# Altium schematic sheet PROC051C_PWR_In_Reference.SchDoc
size 431 x 279 mm; Date: Not shown in title block; ApprovedBy: Not shown in title block; CheckedBy: Not shown in title block; Author: Not shown in title block; CompanyName: Not shown in title block; Engineer: Not shown in title block; Organization: Not shown in title block; Address1: Not shown in title block; Address2: Not shown in title block; Address3: Not shown in title block; Address4: Not shown in title block; DocumentNumber: 4; Revision: Use project parameter SCH_Rev; SheetNumber: 4; SheetTotal: 16; PageSetup: Record=PageOptions¦CenterHorizontal=True¦CenterVertical=True¦PrintScale=1.00¦XCorrection=1.00¦YCorrection=1.00¦PrintKind=0¦BorderSize=5000000¦LeftOffset=0¦BottomOffset=0¦Orientation=2¦PaperLength=1000¦PaperWidth=1000¦Scale=100¦PaperSource=15¦PrintQuality=600¦MediaType=1¦DitherType=10¦PaperKind=Letter¦PrintScaleMode=1
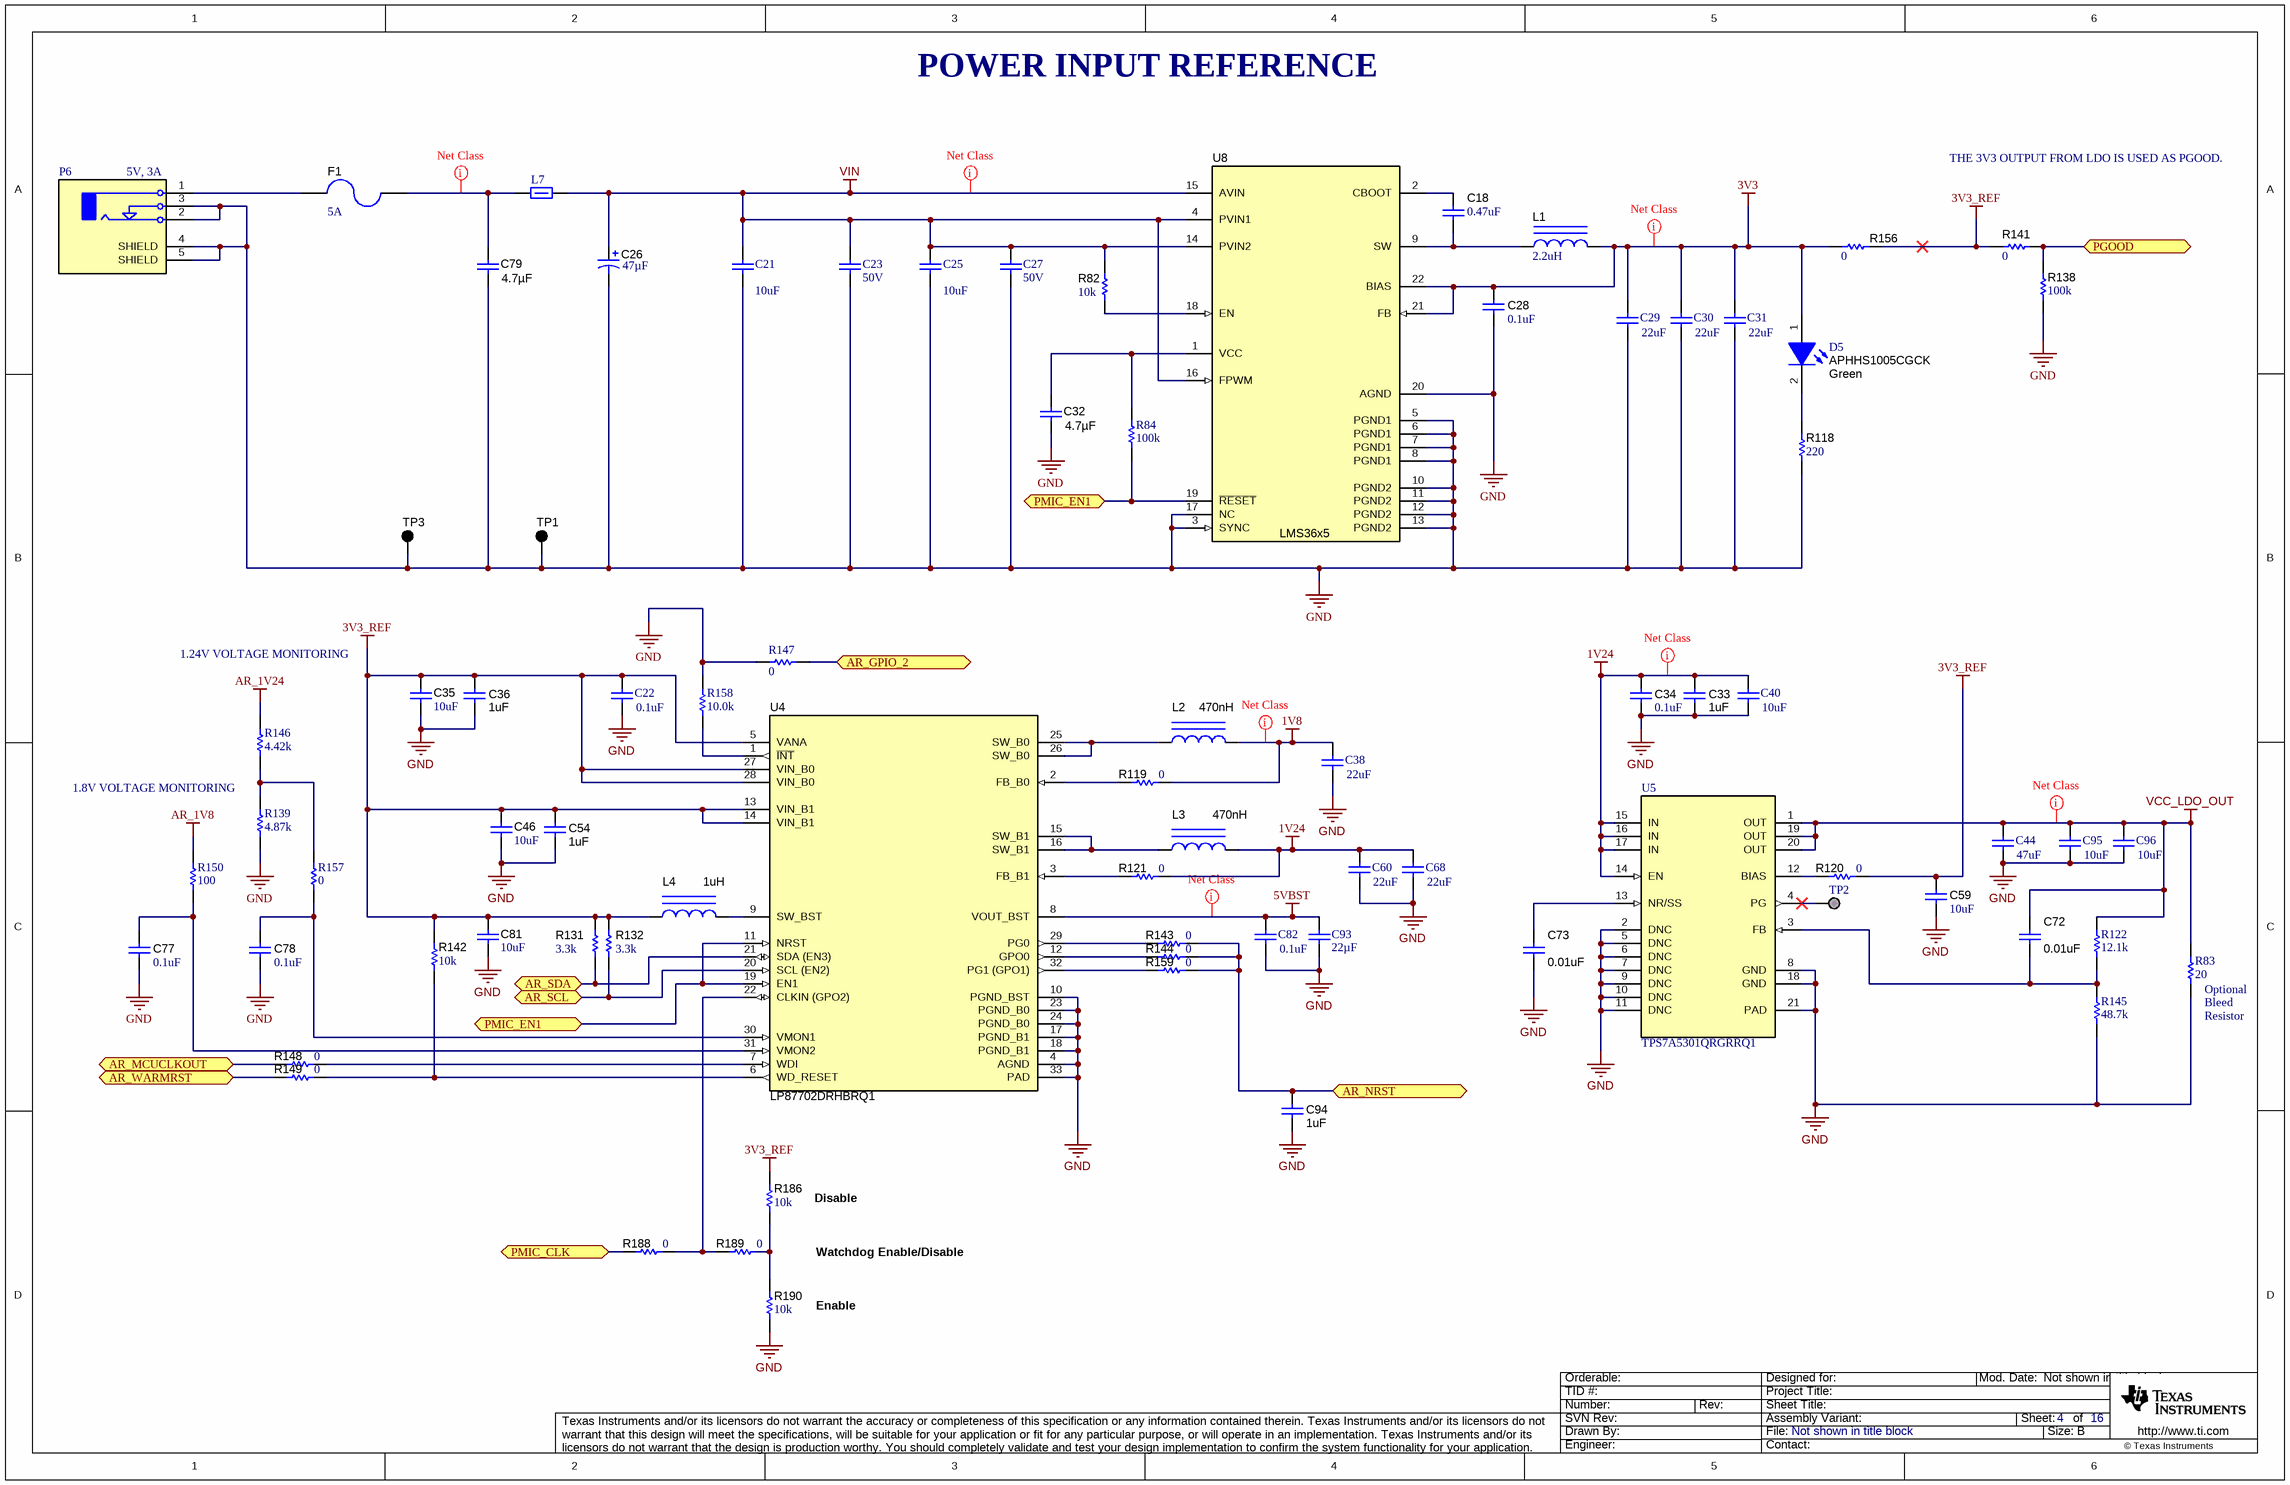
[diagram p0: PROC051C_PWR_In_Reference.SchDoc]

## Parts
C18  ValueDisplayed: 0.47uF  [0402S]  (hidden comment: Capacitor)
C21  ValueDisplayed: 10uF  [1210_280]  (hidden comment: CGA6P1X7R1E106M250AC)
C22  ValueDisplayed: 0.1uF  [0402]  (hidden comment: GCM155R71C104KA55D)
C23  VDC_V: 50V  [0603]  (hidden comment: 06035C473JAT2A)
C25  ValueDisplayed: 10uF  [1210_280]  (hidden comment: CGA6P1X7R1E106M250AC)
C26  ValueDisplayed: 47µF  [3528-21]  (hidden comment: T491B476K010AT)
C27  VDC_V: 50V  [0603]  (hidden comment: 06035C473JAT2A)
C28  ValueDisplayed: 0.1uF  [0402S]  (hidden comment: Capacitor)
C29  ValueDisplayed: 22uF  [1210_280]  (hidden comment: GCM32ER71C226KE19L)
C30  ValueDisplayed: 22uF  [1210_280]  (hidden comment: GCM32ER71C226KE19L)
C31  ValueDisplayed: 22uF  [1210_280]  (hidden comment: GCM32ER71C226KE19L)
C32  ValueDisplayed: 4.7µF  [0805L]  (hidden comment: CGA4J1X7R1E475K125AC)
C33  ValueDisplayed: 1uF  [0603]  (hidden comment: GCM188R71C105KA64D)
C34  ValueDisplayed: 0.1uF  [0402]  (hidden comment: Capacitor)
C35  ValueDisplayed: 10uF  [0805_HV1]  (hidden comment: Capacitor)
C36  ValueDisplayed: 1uF  [0603]  (hidden comment: GCM188R71C105KA64D)
C38  ValueDisplayed: 22uF  [1206_180]  (hidden comment: GCM31CR70J226KE23L)
C40  ValueDisplayed: 10uF  [0805_HV]  (hidden comment: GCM21BR71A106KE22L)
C44  ValueDisplayed: 47uF  [1210_270]  (hidden comment: GCM32ER70J476KE19L)
C46  ValueDisplayed: 10uF  [0805_HV1]  (hidden comment: Capacitor)
C54  ValueDisplayed: 1uF  [0603]  (hidden comment: GCM188R71C105KA64D)
C59  ValueDisplayed: 10uF  [0805_HV]  (hidden comment: Capacitor)
C60  ValueDisplayed: 22uF  [1206_180]  (hidden comment: GCM31CR70J226KE23L)
C68  ValueDisplayed: 22uF  [1206_180]  (hidden comment: GCM31CR70J226KE23L)
C72  ValueDisplayed: 0.01uF  [0402S]  (hidden comment: GCM155R71E103KA37D)
C73  ValueDisplayed: 0.01uF  [0402S]  (hidden comment: GCM155R71E103KA37D)
C77  ValueDisplayed: 0.1uF  [0402]  (hidden comment: Capacitor)
C78  ValueDisplayed: 0.1uF  [0402]  (hidden comment: Capacitor)
C79  ValueDisplayed: 4.7µF  [0805L]  (hidden comment: CGA4J1X7R1E475K125AC)
C81  ValueDisplayed: 10uF  [0805_HV1]  (hidden comment: Capacitor)
C82  ValueDisplayed: 0.1uF  [0402]  (hidden comment: 0402YC104KAT2A)
C93  ValueDisplayed: 22µF  [0805_HV]  (hidden comment: GRT21BR61E226ME13L)
C94  ValueDisplayed: 1uF  [0603]  (hidden comment: GCM188R71C105KA64D)
C95  ValueDisplayed: 10uF  [0805_HV]  (hidden comment: GCM21BR71A106KE22L)
C96  ValueDisplayed: 10uF  [0805_HV]  (hidden comment: GCM21BR71A106KE22L)
D5  APHHS1005CGCK  value Green  [APHHS1005_Green]
F1  0440005.WR  [1206]  (value not drawn)
L1  ValueDisplayed: 2.2uH  [XAL5030]  (hidden comment: XAL5030-222MEB)
L2  ValueDisplayed: 470nH  [DFE252012P]  (hidden comment: DFE252012PD-R47M)
L3  ValueDisplayed: 470nH  [DFE252012P]  (hidden comment: DFE252012PD-R47M)
L4  ValueDisplayed: 1uH  [DFE252012P]  (hidden comment: DFE252012PD-1R0M)
L7  HI2220P601R-10  [2220_345]  (value not drawn)
P6  PJ-051AH  [CUI_PJ-051AH]  (value not drawn)
R82  value 10k  [0402L]  (hidden comment: Resistor)
R83  ValueDisplayed: 20  [0603]  (hidden comment: CRCW060320R0JNEA)
R84  ValueDisplayed: 100k  [0402]  (hidden comment: CRCW0402100KJNED)
R118  ValueDisplayed: 220  [0402]  (hidden comment: CRCW0402220RJNED)
R119  value 0  [0402L]  (hidden comment: Resistor)
R120  value 0  [0402L]  (hidden comment: Resistor)
R121  value 0  [0402L]  (hidden comment: Resistor)
R122  ValueDisplayed: 12.1k  [0402]  (hidden comment: ERA-2AEB1212X)
R131  ValueDisplayed: 3.3k  [0402S]  (hidden comment: Resistor)
R132  ValueDisplayed: 3.3k  [0402S]  (hidden comment: Resistor)
R138  ValueDisplayed: 100k  [0402L]  (hidden comment: CRCW0402100KFKED)
R139  ValueDisplayed: 4.87k  [0402]  (hidden comment: ERA-2AEB4871X)
R141  ValueDisplayed: 0  [0402L]  (hidden comment: ERJ-2GE0R00X)
R142  ValueDisplayed: 10k  [0402]  (hidden comment: CRCW040210K0JNED)
R143  value 0  [0402L]  (hidden comment: Resistor)
R144  value 0  [0402L]  (hidden comment: Resistor)
R145  ValueDisplayed: 48.7k  [0402]  (hidden comment: ERA-2AEB4872X)
R146  ValueDisplayed: 4.42k  [0402]  (hidden comment: ERA-2ARB4421X)
R147  ValueDisplayed: 0  [0402]  (hidden comment: CRCW04020000Z0ED)
R148  value 0  [0402L]  (hidden comment: Resistor)
R149  value 0  [0402L]  (hidden comment: Resistor)
R150  ValueDisplayed: 100  [0402]  (hidden comment: CRCW0402100RFKED)
R156  ValueDisplayed: 0  [2010]  (hidden comment: CRCW20100000Z0EF)
R157  ValueDisplayed: 0  [0402]  (hidden comment: CRCW04020000Z0ED)
R158  ValueDisplayed: 10.0k  [0402]  (hidden comment: CRCW040210K0FKED)
R159  value 0  [0402L]  (hidden comment: Resistor)
R186  ValueDisplayed: 10k  [0402]  (hidden comment: CRCW040210K0JNED)
R188  value 0  [0402L]  (hidden comment: Resistor)
R189  value 0  [0402L]  (hidden comment: Resistor)
R190  ValueDisplayed: 10k  [0402]  (hidden comment: CRCW040210K0JNED)
TP1  5001  [Keystone5001]  (value not drawn)
TP2  TP_H0.45P0.75  [TP_H045P075]  (value not drawn)  (no BOM)
TP3  5001  [Keystone5001]  (value not drawn)
U4  LP87702DRHBRQ1  [RHB0032N]
U5  TPS7A5301QRGRRQ1  [RGR0020A]
U8  LMS36x5  [RNL0022A_NV]

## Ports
AR_GPIO_2, AR_MCUCLKOUT, AR_NRST, AR_SCL, AR_SDA, AR_WARMRST, PGOOD, PMIC_CLK, PMIC_EN1

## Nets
1V8: C38.1 L2.2 R119.1
1V24: C33.2 C34.1 C40.1 C60.1 C68.1 L3.2 R121.1 U5.14(EN) U5.15(IN) U5.16(IN) U5.17(IN)
3V3: C28.1 C29.1 C30.1 C31.1 D5.1(A) L1.2 R156.1 U8.21(FB) U8.22(BIAS)
3V3_REF: C22.1 C35.1 C36.2 C46.1 C54.2 C59.1 C81.1 L4.1 R120.1 R131.2 R132.2 R141.1 R142.2 R156.2 R186.2 U4.5(VANA) U4.13(VIN_B1) U4.14(VIN_B1) U4.27(VIN_B0) U4.28(VIN_B0)
5VBST: C82.1 C93.1 U4.8(VOUT_BST)
AR_1V8: R150.2
AR_1V24: R146.2
GND: C21.2 C22.2 C23.2 C25.2 C26.2(-) C27.2 C28.2 C29.2 C30.2 C31.2 C32.2 C33.1 C34.2 C35.2 C36.1 C38.2 C40.2 C44.2 C46.2 C54.1 C59.2 C60.2 C68.2 C73.2 C77.2 C78.2 C79.2 C81.2 C82.2 C93.2 C94.1 C95.2 C96.2 P6.2(TIP) P6.3(TIP_SWITCH) P6.4(SHIELD) P6.5(SHIELD) R83.1 R118.1 R138.1 R139.1 R145.1 R147.2 R158.2 R190.1 TP1.1 TP3.1 U4.4(AGND) U4.10(PGND_BST) U4.17(PGND_B1) U4.18(PGND_B1) U4.23(PGND_B0) U4.24(PGND_B0) U4.33(PAD) U5.2(DNC) U5.5(DNC) U5.6(DNC) U5.7(DNC) U5.8(GND) U5.9(DNC) U5.10(DNC) U5.11(DNC) U5.18(GND) U5.21(PAD) U8.3(SYNC) U8.5(PGND1) U8.6(PGND1) U8.7(PGND1) U8.8(PGND1) U8.10(PGND2) U8.11(PGND2) U8.12(PGND2) U8.13(PGND2) U8.17(NC) U8.20(AGND)
VCC_LDO_OUT: C44.1 C72.1 C95.1 C96.1 R83.2 R122.2 U5.1(OUT) U5.19(OUT) U5.20(OUT)
VIN: C21.1 C23.1 C25.1 C26.1(+) C27.1 L7.2 R82.1 U8.4(PVIN1) U8.14(PVIN2) U8.15(AVIN) U8.16(FPWM)
AR_GPIO_2: R147.1 ; port AR_GPIO_2
AR_MCUCLKOUT: R148.2 ; port AR_MCUCLKOUT
AR_NRST: C94.2 R143.1 R144.1 R159.1 ; port AR_NRST
AR_SCL: R132.1 U4.20(SCL_(EN2)) ; port AR_SCL
AR_SDA: R131.1 U4.21(SDA_(EN3)) ; port AR_SDA
AR_WARMRST: R149.2 ; port AR_WARMRST
PGOOD: R138.2 R141.2 ; port PGOOD
PMIC_CLK: R188.2 ; port PMIC_CLK
PMIC_EN1: R84.1 U4.11(NRST) U4.19(EN1) U8.19(~{RESET}) ; port PMIC_EN1
NetC18_1: C18.1 U8.2(CBOOT)
NetC18_2: C18.2 L1.1 U8.9(SW)
NetC32_1: C32.1 R84.2 U8.1(VCC)
NetC72_2: C72.2 R122.1 R145.2 U5.3(FB)
NetC73_1: C73.1 U5.13(NR/SS)
NetC77_1: C77.1 R150.1 U4.31(VMON2)
NetC78_1: C78.1 R157.1 U4.30(VMON1)
NetC79_1: C79.1 F1.1 L7.1
NetD5_2: D5.2(K) R118.2
NetF1_2: F1.2 P6.1(SLEEVE)
NetL2_1: L2.1 U4.25(SW_B0) U4.26(SW_B0)
NetL3_1: L3.1 U4.15(SW_B1) U4.16(SW_B1)
NetL4_2: L4.2 U4.9(SW_BST)
NetR82_2: R82.2 U8.18(EN)
NetR119_2: R119.2 U4.2(FB_B0)
NetR120_2: R120.2 U5.12(BIAS)
NetR121_2: R121.2 U4.3(FB_B1)
NetR139_2: R139.2 R146.1 R157.2
NetR142_1: R142.1 R149.1 U4.6(WD_RESET)
NetR143_2: R143.2 U4.29(PG0)
NetR144_2: R144.2 U4.12(GPO0)
NetR148_1: R148.1 U4.7(WDI)
NetR158_1: R158.1 U4.1(~{INT})
NetR159_2: R159.2 U4.32(PG1_(GPO1))
NetR186_1: R186.1 R189.1 R190.2
NetR188_1: R188.1 R189.2 U4.22(CLKIN_(GPO2))
NetTP2_1: TP2.1 U5.4(PG)

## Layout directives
net class Undefined: VCC_LDO_OUT
net class PWR: 1V8, 1V24, 3V3, 5VBST, NetC79_1, VIN

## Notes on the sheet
- POWER INPUT REFERENCE
- THE 3V3 OUTPUT FROM LDO IS USED AS PGOOD.
- (near P6) 5V, 3A
- (near F1) 5A
- 1.24V VOLTAGE MONITORING
- 1.8V VOLTAGE MONITORING
- (near R83) Optional
- (near R83) Bleed
- (near R83) Resistor
- (near R186) Disable
- (near R190) Enable
- Watchdog Enable/Disable

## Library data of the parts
C18 = CMP-0006717-2: CAP, CERM, 0.47 uF, 6.3 V, +/- 10%, X7R, 0402; PartNumber: JMK105B7474KVHF; Manufacturer: Taiyo Yuden; Polarized: N; Value: 0.47uF; U/M: EA; Cap_F: 470nF; Value1: Unknown; VDC_V: 6.3V; TaMin_C: -55°C; TaMax_C: 125°C; Cap_Case: 0402; SizeArea_mm2: 0.5; SizeAreaWB_mm2: 3; SizeX_mm: 1; SizeZ_mm: 0.6; AEC Category: Q200
C21 C25 = CMP-0009155-2: CAP, CERM, 10 uF, 25 V, +/- 20%, X7R, AEC-Q200 Grade 1, 1210; Manufacturer: TDK; TaMin_C: -55°C; Polarized: N; SizeAreaWB_mm2: 14.7; Value1: Unknown; U/M: EA; Value: 10uF; TaMax_C: 125°C; SizeZ_mm: 2.8; SizeX_mm: 3.2; SizeY_mm: 2.5; Cap_Case: 1210; Value2: 25V; SizeArea_mm2: 8; AEC Qualified: Y; Cap_F: 10µF; AEC Grade: 1; AEC Category: Q200
C22 = CMP-0006351-2: CAP, CERM, 0.1 uF, 16 V, +/- 10%, X7R, 0402; Manufacturer: MuRata; TaMin_C: -55°C; Polarized: N; SizeAreaWB_mm2: 3; Value1: Unknown; U/M: EA; Value: 0.1uF; TaMax_C: 125°C; SizeZ_mm: 0.6; SizeX_mm: 1; SizeY_mm: 0.5; Value2: 16V; Cap_F: 100nF; AEC Category: Q200
C23 C27 = CMP-0085252-1: CAP, CERM, 0.047 µF, 50 V,+/- 5%, X7R, 0603; Manufacturer: AVX; Cap_F: 47nF; TaMax_C: 125°C; Value: 0.047uF; SizeX_mm: 1.6; SizeArea_mm2: 1.28; AEC Category: Q200; SizeY_mm: 0.8; Polarized: N; SizeAreaWB_mm2: 4.68; U/M: EA; TaMin_C: -55°C; SizeZ_mm: 1
C26 = CMP-0078216-1: CAP, TA, 47 µF, 10 V, +/- 10%, SMD; Manufacturer: Kemet; TaMin_C: -55°C; Polarized: Y; SizeAreaWB_mm2: 17.1; Value: 47uF; TaMax_C: 125°C; SizeZ_mm: 2.1; SizeX_mm: 3.5; SizeY_mm: 2.8; Value2: 10V; SizeArea_mm2: 9.8; CompType: Capacitor; AEC Qualified: N; AEC Category: Q200
C28 = CMP-0006201-2: CAP, CERM, 0.1 uF, 16 V, +/- 10%, X7R, 0402; PartNumber: 0402YC104KAT2A; Manufacturer: AVX; Polarized: N; Value: 0.1uF; U/M: EA; Cap_F: 100nF; Value1: Unknown; VDC_V: 16V; TaMin_C: -55°C; TaMax_C: 125°C; Cap_Case: 0402; SizeArea_mm2: 0.5; SizeAreaWB_mm2: 3; SizeX_mm: 1; SizeZ_mm: 0.6; AEC Category: Q200
C29-C31 = CMP-0009174-2: CAP, CERM, 22 uF, 16 V, +/- 10%, X7R, 1210; Manufacturer: MuRata; TaMin_C: -55°C; Polarized: N; SizeAreaWB_mm2: 14.7; Value1: Unknown; U/M: EA; Value: 22uF; TaMax_C: 125°C; SizeZ_mm: 2.8; SizeX_mm: 3.2; SizeY_mm: 2.5; Cap_Case: 1210; Value2: 16V; SizeArea_mm2: 8; Cap_F: 22µF; AEC Category: Q200
C32 C79 = CMP-0076706-1: CAP, CERM, 4.7 µF, 25 V,+/- 10%, X7R, AEC-Q200 Grade 1, 0805; Manufacturer: TDK; SizeAreaWB_mm2: 6.75; SizeArea_mm2: 2.5; AEC Qualified: Y; AEC Category: Q200; Value: 4.7uF; TaMax_C: 125°C; SizeZ_mm: 1.45; AEC Grade: 1; Polarized: N; TaMin_C: -55°C; VDC_V: 25V; SizeY_mm: 1.25; U/M: EA; CompType: Capacitor; SizeX_mm: 2.0; Cap_Case: 2x1.25x1.25mm
C33 C36 C54 C94 = CMP-0007136-5: CAP, CERM, 1 uF, 16 V, +/- 10%, X7R, AEC-Q200 Grade 1, 0603; Manufacturer: MuRata; TaMin_C: -55°C; Polarized: N; SizeAreaWB_mm2: 4.68; Value1: Unknown; U/M: EA; Value: 1uF; TaMax_C: 125°C; SizeZ_mm: 1; SizeX_mm: 1.6; SizeY_mm: 0.8; Value2: 16V; SizeArea_mm2: 1.28; AEC Qualified: Y; Cap_F: 1µF; AEC Category: Q200
C34 C77 C78 = CMP-0006201-2: CAP, CERM, 0.1 uF, 16 V, +/- 10%, X7R, 0402; PartNumber: 0402YC104KAT2A; Manufacturer: AVX; Polarized: N; Value: 0.1uF; U/M: EA; Cap_F: 100nF; Value1: Unknown; VDC_V: 16V; TaMin_C: -55°C; TaMax_C: 125°C; SizeArea_mm2: 0.5; SizeAreaWB_mm2: 3; SizeX_mm: 1; SizeZ_mm: 0.6; AEC Category: Q200
C35 C46 C81 = CMP-0007995-2: CAP, CERM, 10 uF, 16 V, +/- 10%, X7R, 0805; PartNumber: CL21B106KOQNNNE; Manufacturer: Samsung Electro-Mechanics; Polarized: N; Value: 10uF; U/M: EA; Cap_F: 10µF; Value1: Unknown; VDC_V: 16V; TaMin_C: -55°C; TaMax_C: 125°C; Cap_Case: 0805; SizeArea_mm2: 2.5; SizeAreaWB_mm2: 6.75; SizeX_mm: 2; SizeY_mm: 1.25; SizeZ_mm: 1.45; AEC Category: Q200
C38 C60 = CMP-0008809-2: CAP, CERM, 22 uF, 6.3 V, +/- 10%, X7R, AEC-Q200 Grade 1, 1206; Manufacturer: MuRata; TaMin_C: -55°C; Polarized: N; SizeAreaWB_mm2: 10.92; Value1: Unknown; U/M: EA; Value: 22uF; TaMax_C: 125°C; SizeZ_mm: 1.8; SizeX_mm: 3.2; SizeY_mm: 1.6; Cap_Case: 1206; Value2: 6.3V; SizeArea_mm2: 5.12; AEC Qualified: Y; Cap_F: 22µF; AEC Grade: 1; AEC Category: Q200
C40 C95 C96 = CMP-0008017-2: CAP, CERM, 10 uF, 10 V, +/- 10%, X7R, 0805; Manufacturer: MuRata; TaMin_C: -55°C; Polarized: N; SizeAreaWB_mm2: 6.75; Value1: Unknown; U/M: EA; Value: 10uF; TaMax_C: 125°C; SizeZ_mm: 1.45; SizeX_mm: 2; SizeY_mm: 1.25; Cap_Case: 0805; Value2: 10V; SizeArea_mm2: 2.5; Cap_F: 10µF; AEC Category: Q200
C44 = CMP-0009172-2: CAP, CERM, 47 uF, 6.3 V, +/- 10%, X7R, AEC-Q200 Grade 1, 1210; Manufacturer: MuRata; TaMin_C: -55°C; Polarized: N; SizeAreaWB_mm2: 14.7; Value1: Unknown; U/M: EA; Value: 47uF; TaMax_C: 125°C; SizeZ_mm: 2.7; SizeX_mm: 3.2; SizeY_mm: 2.5; Cap_Case: 1210; Value2: 6.3V; SizeArea_mm2: 8; AEC Qualified: Y; Cap_F: 47µF; AEC Grade: 1; AEC Category: Q200
C59 = CMP-0008017-2: CAP, CERM, 10 uF, 10 V, +/- 10%, X7R, 0805; PartNumber: GCM21BR71A106KE22L; Manufacturer: MuRata; Polarized: N; Value: 10uF; U/M: EA; Cap_F: 10µF; Value1: Unknown; VDC_V: 10V; TaMin_C: -55°C; TaMax_C: 125°C; Cap_Case: 0805; SizeArea_mm2: 2.5; SizeAreaWB_mm2: 6.75; SizeX_mm: 2; SizeY_mm: 1.25; SizeZ_mm: 1.45; AEC Category: Q200
C68 = CMP-0008809-2: CAP, CERM, 22 uF, 6.3 V, +/- 10%, X7R, AEC-Q200 Grade 1, 1206; Manufacturer: MuRata; TaMin_C: -55°C; Polarized: N; SizeAreaWB_mm2: 10.92; Value1: Unknown; U/M: EA; Value: 22uF; TaMax_C: 125°C; SizeZ_mm: 1.8; SizeX_mm: 3.2; SizeY_mm: 1.6; Cap_Case: 1206; Value2: 6.3V; SizeArea_mm2: 5.12; CompType: Capacitor; AEC Qualified: Y; Cap_F: 22µF; AEC Grade: 1; AEC Category: Q200
C72 C73 = CMP-0006352-2: CAP, CERM, 0.01 uF, 25 V, +/- 10%, X7R, 0402; Manufacturer: MuRata; TaMin_C: -55°C; Polarized: N; SizeAreaWB_mm2: 3; Value1: Unknown; U/M: EA; Value: 0.01uF; TaMax_C: 125°C; SizeZ_mm: 0.6; SizeX_mm: 1; SizeY_mm: 0.5; Cap_Case: 0402; Value2: 25V; CompType: Capacitor; Cap_F: 10nF; AEC Category: Q200
C82 = CMP-0006201-2: CAP, CERM, 0.1 uF, 16 V, +/- 10%, X7R, 0402; Manufacturer: AVX; TaMin_C: -55°C; Polarized: N; SizeAreaWB_mm2: 3; Value1: Unknown; U/M: EA; Value: 0.1uF; TaMax_C: 125°C; SizeZ_mm: 0.6; SizeX_mm: 1; SizeY_mm: 0.5; Value2: 16V; Cap_F: 100nF; AEC Category: Q200
C93 = CMP-0084680-1: CAP, CERM, 22 µF, 25 V,+/- 20%, X5R, AEC-Q200 Grade 3, 0805; Manufacturer: MuRata; SizeX_mm: 2; SizeAreaWB_mm2: 6.75; Cap_Case: 0805; AEC Grade: 3; SizeY_mm: 1.25; SizeArea_mm2: 2.5; SizeZ_mm: 1.45; U/M: EA; Polarized: N; VDC_V: 25V; AEC Category: Q200; Value: 22uF; TaMin_C: -55°C; AEC Qualified: Y; TaMax_C: 85°C
D5 = CMP-0067682-2: LED, Green, SMD; Manufacturer: Kingbright; Io_A: 20mA; Power_TotalModule: 75mW; SizeAreaWB_mm2: 3.0; Vr_V: 5V; Tjmax_C: 85°C; Value1: 0.075W; Angle: 120.0; SizeZ_mm: 0.6; SizeX_mm: 1.0; SizeY_mm: 0.5; Ir_A: 10µA; Vf_V: 2.1V
F1 = CMP-0003458-2: Fuse, 5 A, 32VAC/VDC, SMD; Manufacturer: Littelfuse; Irating_A: 5A; SizeAreaWB_mm2: 10.92; Interrupt_AC: 50A; VAC_V: 32V; SizeZ_mm: 1.35; SizeX_mm: 3.2; SizeY_mm: 1.6; SizeArea_mm2: 5.12; Rtyp_Ohm: 0.012; MeltingTyp: 4.761
L1 = CMP-0061001-2: Inductor, Shielded, Composite, 2.2 µH, 9.2 A, 0.01 ohm, AEC-Q200 Grade 1, SMD; Manufacturer: Coilcraft; Isat: 12.9A @ 30% inductance drop; Irms: 9.2A @ 40C rise; Green_Lifecycle: Not Set; SizeAreaWB_mm2: 54.4544; DCR_ohm: 0.01; Green_REACh: Incomplete; Value: 2.2uH; Imax_A: 9.2A; SizeZ_mm: 3.1; SizeX_mm: 5.28; SizeY_mm: 5.48; SizeArea_mm2: 28.9344; Ind_H: 2.2µH; AEC Qualified: 1; AEC Category: Q200; AEC Grade: Y
L2 L3 = CMP-0058944-1: Inductor, Shielded, 470 nH, 4.7 A, 0.021 ohm, SMD; Manufacturer: MuRata Toko; Isat: 6.1A @ 30% inductance drop; Irms: 4.7A @ 40C rise; SizeAreaWB_mm2: 10.5; DCR_ohm: 0.021; Value: 470nH; Imax_A: 4.7A; SizeZ_mm: 1.2; SizeX_mm: 2.5; SizeY_mm: 2; SizeArea_mm2: 5; AEC Category: Q200
L4 = CMP-0058938-1: Inductor, Shielded, 1 uH, 3.8 A, 0.035 ohm, AEC-Q200 Grade 1, SMD; Manufacturer: MuRata Toko; Isat: 4.5A @ 30% inductance drop; Irms: 3.8A @ 40C rise; SizeAreaWB_mm2: 10.5; DCR_ohm: 0.035; Value: 1uH; Imax_A: 3.8A; SizeZ_mm: 1.2; SizeX_mm: 2.5; SizeY_mm: 2; SizeArea_mm2: 5; Ind_H: 1µH; AEC Qualified: Y; AEC Grade: 1; AEC Category: Q200
L7 = CMP-0003388-1: Ferrite Bead, 600 ohm @ 100 MHz, 4 A, 2220; Manufacturer: Laird-Signal Integrity Products; Ztyp@1GHz_Ohm: 106; ZTyp@100MHz_Ohm: 600; SizeAreaWB_mm2: 53.96; DCR_ohm: 0.025; Value1: 0.025 ohm; Value: 600 ohm; Imax_A: 4A; SizeZ_mm: 3.45; SizeX_mm: 5.6; SizeY_mm: 5.1; SizeArea_mm2: 28.56
P6 = CMP-0081851-1: DC Power Jack, R/A, TH; Manufacturer: CUI Inc.; Gender: Male; Cert_UL: Y; Current_A: 5A; Voltage_V: 24V
R82 = CMP-0026825-5: RES, 10 k, 5%, 0.063 W, AEC-Q200 Grade 0, 0402; PartNumber: CRCW040210K0JNED; Manufacturer: Vishay-Dale; Value_Code: 10k0; Power_W: 63mW; Value2: 0.063W; VDC_V: 50V; TempCo: 200 ppm/C; EIA_Code: E24; AEC Category: Q200; AEC Grade: 0; AEC Qualified: Y; SizeArea_mm2: 0.5; SizeX_mm: 1; SizeZ_mm: 0.6
R83 = CMP-0025754-4: RES, 20, 5%, 0.1 W, AEC-Q200 Grade 0, 0603; Manufacturer: Vishay-Dale; Power_W: 100mW; TempCo: 200 ppm/C; Value_Code: 20R0; Value: 20; EIA_Code: E24; SizeX_mm: 1.6; SizeY_mm: 0.8; SizeZ_mm: 1; Value2: 0.1W; SizeArea_mm2: 1.28; AEC Qualified: Y; VDC_V: 75V; AEC Category: Q200; AEC Grade: 0
R84 = CMP-0026823-3: RES, 100 k, 5%, 0.063 W, AEC-Q200 Grade 0, 0402; Manufacturer: Vishay-Dale; Power_W: 63mW; TempCo: 200 ppm/C; Value: 100k; EIA_Code: E24; SizeX_mm: 1; SizeY_mm: 0.5; SizeZ_mm: 0.6; Value2: 0.063W; AEC Qualified: Y; VDC_V: 50V; AEC Category: Q200; AEC Grade: 0
R118 = CMP-0026878-3: RES, 220, 5%, 0.063 W, AEC-Q200 Grade 0, 0402; Manufacturer: Vishay-Dale; Power_W: 63mW; TempCo: 200 ppm/C; Value_Code: 220R; Value: 220; EIA_Code: E24; SizeX_mm: 1; SizeY_mm: 0.5; SizeZ_mm: 0.6; Value2: 0.063W; AEC Qualified: Y; VDC_V: 50V; AEC Category: Q200; AEC Grade: 0
R119-R121 R143 R144 R148 R149 R159 R188 R189 = CMP-0026822-3: RES, 0, 5%, 0.063 W, AEC-Q200 Grade 0, 0402; PartNumber: CRCW04020000Z0ED; Manufacturer: Vishay-Dale; Value_Code: 0000; Power_W: 63mW; Value2: 0.063W; VDC_V: 50V; TempCo: 200 ppm/C; EIA_Code: E24; AEC Category: Q200; AEC Qualified: Y; SizeArea_mm2: 0.5; SizeX_mm: 1; SizeZ_mm: 0.6
R122 = CMP-0083631-1: RES, 12.1 k, 0.1%, 0.063 W, AEC-Q200 Grade 0, 0402; Manufacturer: Panasonic; Power_W: 63mW; TempCo: 25 ppm/C; SizeAreaWB_mm2: 3; Value_Code: 12k1; Value: 12.1k; EIA_Code: E192; SizeX_mm: 1; SizeY_mm: 0.5; SizeZ_mm: 0.6; Value2: 0.063W; CompType: Resistor; AEC Qualified: Y; VDC_V: 50V; AEC Grade: 0; AEC Category: Q200
R131 R132 = CMP-0026918-5: RES, 3.3 k, 5%, 0.063 W, AEC-Q200 Grade 0, 0402; PartNumber: CRCW04023K30JNED; Manufacturer: Vishay-Dale; Value: 3.3k; Value_Code: 3k30; Power_W: 63mW; Value2: 0.063W; VDC_V: 50V; TempCo: 200 ppm/C; SizeArea_mm2: 0.5; SizeX_mm: 1; SizeZ_mm: 0.6; EIA_Code: E24; AEC Category: Q200; AEC Qualified: Y; AEC Grade: 0
R138 = CMP-0025950-3: RES, 100 k, 1%, 0.063 W, AEC-Q200 Grade 0, 0402; Manufacturer: Vishay-Dale; Power_W: 63mW; TempCo: 100 ppm/C; Value: 100k; EIA_Code: E96; SizeX_mm: 1; SizeY_mm: 0.5; SizeZ_mm: 0.6; Value2: 0.063W; AEC Qualified: Y; VDC_V: 50V; AEC Category: Q200; AEC Grade: 0
R139 = CMP-0026781-1: RES, 4.87 k, 0.1%, 0.062 W, AEC-Q200 Grade 0, 0402; Manufacturer: Panasonic; Power_W: 62mW; TempCo: 25 ppm/C; Value_Code: 4k87; U/M: EA; Value: 4.87k; EIA_Code: E192; SizeX_mm: 1; SizeY_mm: 0.5; SizeZ_mm: 0.6; Value2: 0.062W; AEC Qualified: Y; VDC_V: 25V; AEC Grade: 0; AEC Category: Q200
R141 = CMP-0026992-3: RES, 0, 5%, 0.1 W, AEC-Q200 Grade 0, 0402; Manufacturer: Panasonic; Power_W: 100mW; TempCo: 600 ppm/C; Value_Code: 0000; Value: 0; EIA_Code: E24; SizeX_mm: 1; SizeY_mm: 0.5; SizeZ_mm: 0.6; Value2: 0.1W; AEC Qualified: Y; VDC_V: 50V; AEC Category: Q200; SizeAreaWB_mm2: 3
R142 R186 R190 = CMP-0026825-5: RES, 10 k, 5%, 0.063 W, AEC-Q200 Grade 0, 0402; Manufacturer: Vishay-Dale; Power_W: 63mW; TempCo: 200 ppm/C; Value_Code: 10k0; Value: 10k; EIA_Code: E24; SizeX_mm: 1; SizeY_mm: 0.5; SizeZ_mm: 0.6; Value2: 0.063W; AEC Qualified: Y; VDC_V: 50V; AEC Category: Q200; AEC Grade: 0
R145 = CMP-0083632-1: RES, 48.7 k, 0.1%, 0.063 W, AEC-Q200 Grade 0, 0402; Manufacturer: Panasonic; Power_W: 63mW; TempCo: 25 ppm/C; SizeAreaWB_mm2: 3; Value_Code: 48k7; Value: 48.7k; EIA_Code: E192; SizeX_mm: 1; SizeY_mm: 0.5; SizeZ_mm: 0.6; Value2: 0.063W; AEC Qualified: Y; VDC_V: 50V; AEC Grade: 0; AEC Category: Q200
R146 = CMP-0083657-1: RES, 4.42 k, 0.1%, 0.063 W, AEC-Q200 Grade 0, 0402; Manufacturer: Panasonic; Value_Code: 4k42; SizeAreaWB_mm2: 3; SizeArea_mm2: 0.5; AEC Qualified: Y; AEC Category: Q200; Value: 4.42k; SizeZ_mm: 0.6; EIA_Code: E192; TempCo: 10 ppm/C; AEC Grade: 0; Power_W: 63mW; Value2: 0.063W; SizeX_mm: 1
R147 = CMP-0026822-3: RES, 0, 5%, 0.063 W, AEC-Q200 Grade 0, 0402; Manufacturer: Vishay-Dale; Power_W: 63mW; TempCo: 200 ppm/C; Value_Code: 0000; Value: 0; EIA_Code: E24; SizeX_mm: 1; SizeY_mm: 0.5; SizeZ_mm: 0.6; Value2: 0.063W; AEC Qualified: Y; VDC_V: 50V; AEC Category: Q200
R150 = CMP-0025951-3: RES, 100, 1%, 0.063 W, AEC-Q200 Grade 0, 0402; Manufacturer: Vishay-Dale; Power_W: 63mW; TempCo: 100 ppm/C; Value_Code: 100R; Value: 100; EIA_Code: E96; SizeX_mm: 1; SizeY_mm: 0.5; SizeZ_mm: 0.6; Value2: 0.063W; AEC Qualified: Y; VDC_V: 50V; AEC Category: Q200; AEC Grade: 0
R156 = CMP-0016044-3: RES, 0, 5%, 0.75 W, AEC-Q200 Grade 0, 2010; Manufacturer: Vishay-Dale; Power_W: 750mW; TempCo: ppm/C; Value_Code: 0000; Value: 0; EIA_Code: E24; SizeX_mm: 5; SizeY_mm: 2.5; SizeZ_mm: 1.66; Value2: 0.75W; SizeArea_mm2: 12.5; CompType: Resistor; AEC Qualified: Y; AEC Category: Q200
R157 = CMP-0026822-3: RES, 0, 5%, 0.063 W, AEC-Q200 Grade 0, 0402; Manufacturer: Vishay-Dale; Power_W: 63mW; TempCo: 200 ppm/C; Value_Code: 0000; Value: 0; EIA_Code: E24; SizeX_mm: 1; SizeY_mm: 0.5; SizeZ_mm: 0.6; Value2: 0.063W; CompType: Resistor; AEC Qualified: Y; VDC_V: 50V; AEC Category: Q200
R158 = CMP-0025958-3: RES, 10.0 k, 1%, 0.063 W, AEC-Q200 Grade 0, 0402; Manufacturer: Vishay-Dale; Power_W: 63mW; TempCo: 100 ppm/C; Value_Code: 10k0; Value: 10.0k; EIA_Code: E96; Res_ohm: 10k; SizeX_mm: 1; SizeY_mm: 0.5; SizeZ_mm: 0.6; Value2: 0.063W; AEC Qualified: Y; VDC_V: 50V; AEC Category: Q200; AEC Grade: 0
TP1 TP3 = CMP-0055138-1: Test Point, Miniature, Black, TH; Manufacturer: Keystone; CNHeader: FALSE; Green_Lifecycle: Active; Green_REACh: Passed; ContactFinish: Silver; CT: TRUE
TP2 = CMP-0003719-1: Testpoint; Manufacturer: Texas Instruments; CompType: Pad
U4 = CMP-0078631-1: Boost and Dual Buck Regulators With Diagnostic Functions, RHB0032N (VQFN-32); Manufacturer: Texas Instruments; SizeArea_mm2: 25; SizeAreaWB_mm2: 49; SizeX_mm: 5; SizeZ_mm: 0.9; CompType: IC; AEC Category: Q200; AEC Qualified: Y
U5 = CMP-0077268-2: Automotive 3A High-Accuracy Low-Noise Low-Dropout (LDO) Voltage Regulator, RGR0020A (VQFN-20); Manufacturer: Texas Instruments; SizeAreaWB_mm2: 20.25; SizeZ_mm: 1.0; SizeX_mm: 3.5; SizeArea_mm2: 12.25; CompType: IC; AEC Qualified: Y; AEC Category: Q200
U8 = CMP-0076346-4: 2.5A, 36 V Synchronous, 2.1MHz, Automotive Step Down DC-DC Converter, RNL0022A (VQFN-HR-22); PartNumber: LM536253QRNLRQ1; Alternate PartNumber: LM536253QRNLTQ1; Manufacturer: Texas Instruments; SizeArea_mm2: 20.0; SizeAreaWB_mm2: 42.0; SizeX_mm: 4.0; SizeY_mm: 5.0; SizeZ_mm: 0.9; CompType: IC; AEC Category: Q200; AEC Qualified: Y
